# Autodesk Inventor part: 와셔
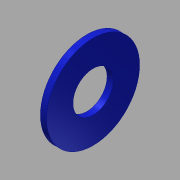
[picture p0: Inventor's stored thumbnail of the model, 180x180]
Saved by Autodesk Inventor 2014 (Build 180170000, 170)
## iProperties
Created: 2015-12
Part Number: 와셔
Material: 스테인리스강
Document SubType Name: Modeling
Designer: mduedu
Density: 8.08 g/cm^3
Appearance: Blue - Wall Paint - Glossy
Author: mduedu
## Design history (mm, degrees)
sketch "스케치1"
  geometry: C1 r 3.25 at (0, 0); C2 r 7.5 at (0, 0); 1 further point
  constraints: 2 centre point, 2 coincident
  dimensions: "d0" = 6.5 diameter of C1; "d1" = 15 diameter of C2
extrude "돌출1" new body sketch "스케치1" stored distance "d2" = 1; taper "d3" = 0 deg
node "솔리드1"
